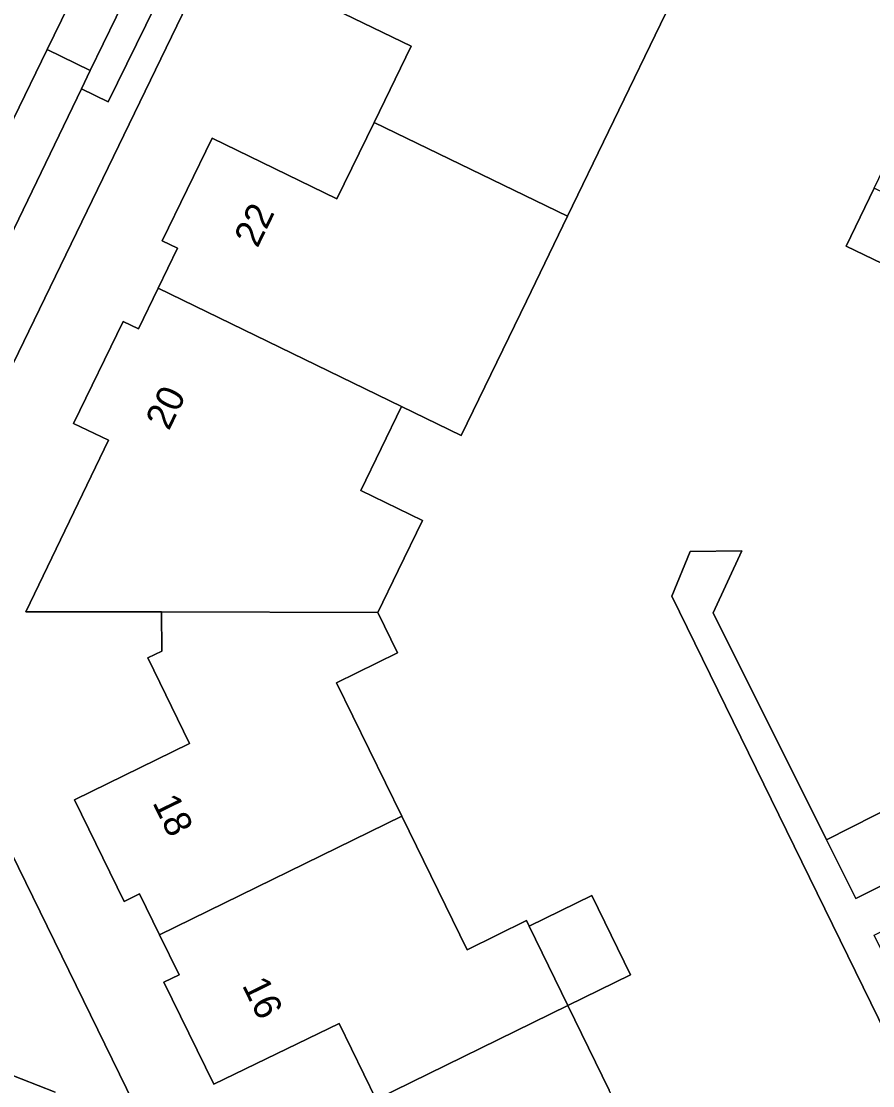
# Model space of a CAD drawing. Extents: x 160455 to 162082, y 388339 to 389736.
# Drawn here: x 160706.38 to 160737.7, y 388927.38 to 388966.52 of the extents above; entities that cross this region are included whole.
import ezdxf

# ---------------------------------------------------------------- set-up
doc = ezdxf.new("R2010")
doc.units = 0
for name, color, linetype in [('IMGEO_Erf', 7, 'Continuous'), ('IMGEO_Pand', 7, 'Continuous'), ('IMGEO_Pand_nummerreeks', 7, 'Continuous'), ('IMGEO_Parkeervlak_open', 7, 'Continuous'), ('IMGEO_Rijbaan_lokaal_gesloten', 7, 'Continuous'), ('IMGEO_Voetpad_open', 7, 'Continuous')]:
    doc.layers.add(name, color=color, linetype=linetype)

msp = doc.modelspace()

# ---------------------------------------------------------------- linework, layer by layer
at = {"layer": 'IMGEO_Erf'}
for points in [[(160729.207, 389001.634), (160728.414, 389000), (160702.377, 388946.323)], [(160719.442, 388926.87), (160718.071, 388929.671), (160713.469, 388927.434), (160711.631, 388931.184), (160712.196, 388931.461), (160711.473, 388932.933), (160710.737, 388934.434), (160710.171, 388934.157), (160708.337, 388937.896), (160712.574, 388939.963), (160711.044, 388943.11), (160711.548, 388943.355), (160711.543, 388944.812), (160706.546, 388944.81), (160709.588, 388951.115), (160708.309, 388951.732), (160710.13, 388955.488), (160710.697, 388955.213), (160711.423, 388956.71), (160712.133, 388958.175), (160711.566, 388958.45), (160713.399, 388962.223), (160717.995, 388959.99), (160719.363, 388962.801), (160720.73, 388965.612), (160716.124, 388967.84)], [(160730.273, 388967.2), (160727.983, 388962.473), (160726.472, 388959.354), (160724.962, 388956.236), (160722.567, 388951.291), (160720.369, 388952.362), (160718.869, 388949.265), (160721.141, 388948.165), (160720.249, 388946.323), (160719.502, 388944.782), (160720.227, 388943.3), (160717.981, 388942.202), (160720.381, 388937.293), (160722.781, 388932.384), (160724.962, 388933.451), (160725.061, 388933.248), (160727.367, 388934.375), (160728.793, 388931.459), (160726.489, 388930.328), (160728.012, 388927.214)], [(160744.386, 388916.63), (160730.313, 388945.38), (160730.986, 388947.021), (160732.891, 388947.051), (160731.827, 388944.767), (160736.003, 388936.427), (160739.605, 388938.247), (160740.666, 388936.058), (160748.671, 388939.936), (160747.367, 388944.564), (160744.531, 388943.789), (160743.289, 388948.335), (160746.348, 388948.298), (160746.964, 388952.951), (160744.035, 388953.122), (160744.612, 388957.523), (160745.144, 388957.349), (160747.683, 388961.75), (160749.886, 388965.515)], [(160702.295, 388943.534), (160746.543, 388853.042), (160750.115, 388854.798), (160751.768, 388851.437), (160755.566, 388854.723), (160761.578, 388855.902), (160765.312, 388848.254), (160760.001, 388845.647), (160754.69, 388843.04), (160753.115, 388846.244), (160750.513, 388844.965), (160752.505, 388840.773)]]:
    msp.add_lwpolyline(points, dxfattribs=at)
msp.add_lwpolyline([(160738.778, 388962.513), (160742.389, 388960.763), (160741.364, 388958.635), (160740.344, 388956.517), (160736.729, 388958.258), (160737.754, 388960.386)], close=True, dxfattribs=at)
at = {"layer": 'IMGEO_Pand'}
for points in [[(160726.472, 388959.354), (160727.983, 388962.473), (160730.273, 388967.2), (160728.074, 388968.266), (160728.172, 388968.469), (160719.228, 388972.806), (160718.507, 388971.316), (160717.94, 388971.59), (160716.124, 388967.84), (160720.73, 388965.612), (160719.363, 388962.801)], [(160726.472, 388959.354), (160719.363, 388962.801), (160717.995, 388959.99), (160713.399, 388962.223), (160711.566, 388958.45), (160712.133, 388958.175), (160711.423, 388956.71), (160720.369, 388952.362), (160722.567, 388951.291), (160724.962, 388956.236)], [(160741.364, 388958.635), (160737.754, 388960.386), (160736.729, 388958.258), (160740.344, 388956.517)], [(160720.369, 388952.362), (160711.423, 388956.71), (160710.697, 388955.213), (160710.13, 388955.488), (160708.309, 388951.732), (160709.588, 388951.115), (160706.546, 388944.81), (160711.543, 388944.812), (160719.502, 388944.782), (160720.249, 388946.323), (160721.141, 388948.165), (160718.869, 388949.265)], [(160719.502, 388944.782), (160711.543, 388944.812), (160711.548, 388943.355), (160711.044, 388943.11), (160712.574, 388939.963), (160708.337, 388937.896), (160710.171, 388934.157), (160710.737, 388934.434), (160711.473, 388932.933), (160720.381, 388937.293), (160717.981, 388942.202), (160720.227, 388943.3)], [(160737.085, 388934.266), (160740.666, 388936.058), (160739.605, 388938.247), (160736.003, 388936.427)], [(160725.061, 388933.248), (160724.962, 388933.451), (160722.781, 388932.384), (160720.381, 388937.293), (160711.473, 388932.933), (160712.196, 388931.461), (160711.631, 388931.184), (160713.469, 388927.434), (160718.071, 388929.671), (160719.442, 388926.87), (160726.489, 388930.328)], [(160725.061, 388933.248), (160726.489, 388930.328), (160728.793, 388931.459), (160727.367, 388934.375)], [(160726.489, 388930.328), (160719.442, 388926.87), (160720.813, 388924.069), (160716.205, 388921.838), (160718.045, 388918.085), (160718.61, 388918.362), (160719.343, 388916.864), (160728.231, 388921.239), (160730.401, 388922.33), (160728.012, 388927.214)]]:
    msp.add_lwpolyline(points, close=True, dxfattribs=at)
at = {"layer": 'IMGEO_Parkeervlak_open'}
for points in [[(160711.783, 388970.605), (160710.203, 388971.374), (160707.335, 388965.483), (160708.921, 388964.71)], [(160708.596, 388964.04), (160708.921, 388964.71), (160707.335, 388965.483), (160703.612, 388957.837), (160702.227, 388954.981), (160703.837, 388954.2), (160704.131, 388954.813)]]:
    msp.add_lwpolyline(points, close=True, dxfattribs=at)
msp.add_lwpolyline([(160707.629, 388927.15), (160705.759, 388927.875), (160705.639, 388927.943), (160705.518, 388928.008), (160706.228, 388926.593), (160707.087, 388924.788), (160708.698, 388925.555), (160708.463, 388926.045), (160708.184, 388926.626)], dxfattribs=at)
at = {"layer": 'IMGEO_Rijbaan_lokaal_gesloten'}
msp.add_lwpolyline([(160716.684, 388995.115), (160711.98, 388985.4), (160709.111, 388979.474), (160708.825, 388978.885), (160703.649, 388968.231), (160700.994, 388962.767), (160699.556, 388959.806), (160696.1, 388952.612), (160695.01, 388950.344), (160699.018, 388948.363), (160700.698, 388951.828), (160702.227, 388954.981), (160703.612, 388957.837), (160707.335, 388965.483), (160710.203, 388971.374), (160713.063, 388977.247), (160714.914, 388981.07), (160717.76, 388986.947), (160722.795, 388997.343)], dxfattribs=at)
at = {"layer": 'IMGEO_Voetpad_open'}
for points in [[(160702.377, 388946.323), (160728.414, 389000), (160729.207, 389001.634)], [(160726.244, 389000.376), (160727.238, 388999.89), (160725.121, 388995.564), (160724.133, 388996.048), (160719.66, 388986.831), (160720.668, 388986.338), (160716.954, 388978.748), (160715.966, 388979.232), (160712.024, 388971.102), (160713.035, 388970.607), (160709.584, 388963.556), (160708.596, 388964.04), (160704.131, 388954.813), (160705.119, 388954.329), (160703.003, 388950.006), (160702.046, 388950.474), (160701.817, 388950.065)], [(160759.101, 388945.008), (160756.236, 388943.603), (160751.737, 388941.422), (160748.671, 388939.936), (160740.666, 388936.058), (160737.085, 388934.266), (160736.003, 388936.427), (160731.827, 388944.767), (160732.891, 388947.051), (160730.986, 388947.021), (160730.313, 388945.38), (160744.386, 388916.63), (160745.465, 388917.158), (160743.899, 388920.357), (160742.852, 388922.496), (160741.823, 388924.598), (160738.811, 388930.755), (160737.751, 388932.921), (160741.344, 388934.679), (160745.529, 388936.703)], [(160750.513, 388844.965), (160746.543, 388853.042), (160702.295, 388943.534)], [(160699.647, 388935.048), (160700.848, 388934.173), (160700.533, 388933.771), (160702.245, 388932.077), (160703.057, 388931.096), (160704.831, 388928.646), (160705.103, 388928.339), (160705.518, 388928.008), (160705.639, 388927.943), (160705.759, 388927.875), (160707.629, 388927.15)]]:
    msp.add_lwpolyline(points, dxfattribs=at)
msp.add_lwpolyline([(160713.035, 388970.607), (160712.024, 388971.102), (160711.783, 388970.605), (160708.921, 388964.71), (160708.596, 388964.04), (160709.584, 388963.556)], close=True, dxfattribs=at)

# ---------------------------------------------------------------- texts
at = {"layer": 'IMGEO_Pand_nummerreeks'}
for s, rotation, p in [('22', 64.0886, (160715.07, 388958.157)), ('20', 64.1369, (160711.811, 388951.439)), ('18', 296.1282, (160711.194, 388937.794)), ('16', 296.1095, (160714.489, 388931.078))]:
    msp.add_text(s, height=1, rotation=rotation, dxfattribs=at).set_placement(p)

doc.saveas('drawing.dxf')
